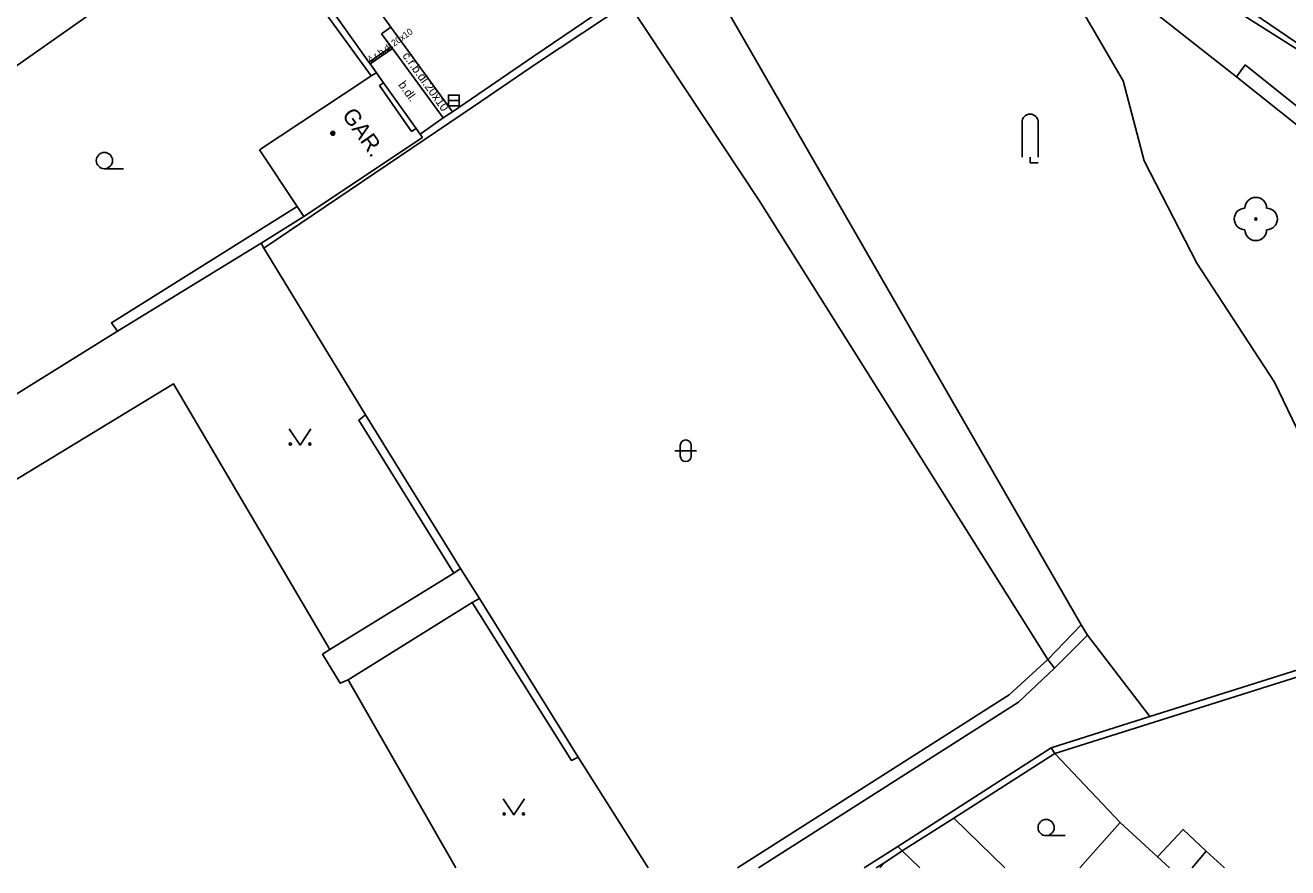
# Model space of a CAD drawing. Extents: x -600391 to -599491, y -1160176 to -1159402.
# Drawn here: x -599722.1 to -599663.7, y -1160176.1 to -1160137.1 of the extents above; entities that cross this region are included whole.
import ezdxf

# ---------------------------------------------------------------- set-up
doc = ezdxf.new("R2010")
doc.units = 0
for name, color, linetype in [('Level 10', 7, 'Continuous'), ('Level 11', 7, 'Continuous'), ('Level 21', 7, 'Continuous'), ('Level 22', 7, 'Continuous'), ('Level 27', 7, 'Continuous'), ('Level 36', 7, 'Continuous'), ('Level 39', 7, 'Continuous'), ('Level 40', 7, 'Continuous'), ('Level 41', 7, 'Continuous'), ('Level 5', 7, 'Continuous'), ('Level 6', 7, 'Continuous'), ('Level 7', 7, 'Continuous'), ('Level 8', 7, 'Continuous'), ('Level 9', 7, 'Continuous')]:
    doc.layers.add(name, color=color, linetype=linetype)

msp = doc.modelspace()

# ---------------------------------------------------------------- linework, layer by layer
at = {"layer": 'Level 10'}
for points in [[(-599729.36, -1160103.71), (-599727.49, -1160106.28), (-599726.09, -1160108.2), (-599720.65, -1160115.64), (-599705.17, -1160137.22)], [(-599694.45, -1160135.76), (-599698.57, -1160138.57), (-599702.33, -1160141.13)], [(-599705.17, -1160137.22), (-599702.33, -1160141.13)]]:
    msp.add_lwpolyline(points, dxfattribs=at)
at = {"layer": 'Level 11'}
for p, q in [((-599702.167, -1160176.079), (-599707.15, -1160167.39)), ((-599696.52, -1160170.96), (-599693.276, -1160176.079)), ((-599679.16, -1160173.78), (-599676.795, -1160176.079)), ((-599680.727, -1160176.079), (-599681.54, -1160175.3)), ((-599667.49, -1160175.31), (-599668.146, -1160176.079)), ((-599666.651, -1160176.079), (-599667.49, -1160175.31)), ((-599682.35, -1160175.83), (-599682.571, -1160176.079))]:
    msp.add_line(p, q, dxfattribs=at)
for points in [[(-599709.31, -1160094.1), (-599694.08, -1160114.15), (-599675.64, -1160129.54), (-599674.089, -1160130.598), (-599661.43, -1160139.23), (-599660.86, -1160139.62), (-599659.78, -1160140.32), (-599650.8, -1160146.17), (-599648.69, -1160147.17), (-599644.71, -1160148.89)], [(-599692.11, -1160132.12), (-599673.27, -1160164.85)], [(-599673.73, -1160133.49), (-599668.38, -1160137.71), (-599666.09, -1160139.52), (-599663.05, -1160141.94), (-599657.72, -1160146.18)], [(-599705.17, -1160137.22), (-599705.6, -1160137.53)], [(-599705.6, -1160137.53), (-599705.16, -1160138.13), (-599705.1, -1160138.21), (-599702.75, -1160141.42)], [(-599706.19, -1160138.84), (-599705.16, -1160138.13)], [(-599706.13, -1160138.92), (-599705.1, -1160138.21)], [(-599665.69, -1160138.97), (-599666.09, -1160139.52)], [(-599657.58, -1160145.46), (-599665.69, -1160138.97)], [(-599703.82, -1160142.17), (-599702.75, -1160141.42), (-599702.45, -1160141.21), (-599702.33, -1160141.13)], [(-599688.15, -1160145.23), (-599674.81, -1160166.46)], [(-599711.16, -1160147.21), (-599711.04, -1160147.44)], [(-599711.04, -1160147.44), (-599706.35, -1160155.14)], [(-599707.99, -1160165.99), (-599715.22, -1160153.71), (-599749.25, -1160174.4)], [(-599702.27, -1160162.46), (-599706.66, -1160155.39), (-599706.35, -1160155.14)], [(-599706.35, -1160155.14), (-599701.96, -1160162.24)], [(-599702.27, -1160162.46), (-599701.96, -1160162.24)], [(-599701.96, -1160162.24), (-599701.08, -1160163.64)], [(-599707.99, -1160165.99), (-599702.27, -1160162.46)], [(-599701.42, -1160163.81), (-599707.15, -1160167.39)], [(-599701.08, -1160163.64), (-599701.42, -1160163.81)], [(-599696.52, -1160170.96), (-599696.83, -1160171.12), (-599701.42, -1160163.81)], [(-599701.08, -1160163.64), (-599696.52, -1160170.96)], [(-599674.81, -1160166.46), (-599673.27, -1160164.85)], [(-599673.27, -1160164.85), (-599672.98, -1160165.32)], [(-599674.5, -1160166.86), (-599672.98, -1160165.32)], [(-599672.98, -1160165.32), (-599670.09, -1160169.08)], [(-599707.15, -1160167.39), (-599707.51, -1160167.55), (-599708.33, -1160166.21), (-599707.99, -1160165.99)], [(-599689.153, -1160176.079), (-599676.6, -1160168.08), (-599674.81, -1160166.46)], [(-599688.183, -1160176.079), (-599676.16, -1160168.43), (-599674.5, -1160166.86)], [(-599674.81, -1160166.46), (-599674.5, -1160166.86)], [(-599674.49, -1160170.79), (-599674.65, -1160170.54)], [(-599671.47, -1160173.99), (-599674.49, -1160170.79)], [(-599667.49, -1160175.31), (-599668.56, -1160174.31), (-599669.74, -1160175.58)], [(-599681.75, -1160175.09), (-599681.54, -1160175.3)]]:
    msp.add_lwpolyline(points, dxfattribs=at)
at = {"layer": 'Level 21'}
msp.add_lwpolyline([(-599632.22, -1160163.23), (-599625.63, -1160162.75), (-599627.08, -1160161.05), (-599631.51, -1160158.07), (-599634.33, -1160155.48), (-599639.05, -1160154.4), (-599647.01, -1160155.58), (-599651.94, -1160159.14), (-599660.68, -1160161.21), (-599664.34, -1160153.64), (-599667.93, -1160148.13), (-599670.36, -1160143.4), (-599671.33, -1160139.71), (-599675.67, -1160132.25), (-599678.77, -1160130.69), (-599683.2, -1160135.35), (-599690.37, -1160125.58), (-599695.06, -1160124.12), (-599698.92, -1160119.17), (-599710.69, -1160100.66)], dxfattribs=at)
at = {"layer": 'Level 22'}
msp.add_circle((-599665.2, -1160146.09), 0.05, dxfattribs=at)
for centre, start, end in [((-599665.2, -1160145.59), 0, 180), ((-599665.7, -1160146.09), 90, 270), ((-599664.7, -1160146.09), 270, 90), ((-599665.2, -1160146.59), 180, 0)]:
    msp.add_arc(centre, 0.5, start, end, dxfattribs=at)
at = {"layer": 'Level 27'}
msp.add_line((-599702.51, -1160140.61), (-599702.01, -1160140.61), dxfattribs=at)
msp.add_lwpolyline([(-599702.51, -1160140.86), (-599702.01, -1160140.86), (-599702.01, -1160140.36), (-599702.51, -1160140.36)], close=True, dxfattribs=at)
at = {"layer": 'Level 36'}
for p, q in [((-599676.005, -1160141.615), (-599676.005, -1160143.24)), ((-599675.255, -1160141.615), (-599675.255, -1160143.24)), ((-599718.41, -1160143.765), (-599717.535, -1160143.765)), ((-599692.046, -1160156.806), (-599691.046, -1160156.806)), ((-599691.796, -1160156.556), (-599691.796, -1160157.056)), ((-599691.296, -1160156.556), (-599691.296, -1160157.056)), ((-599674.89, -1160174.595), (-599674.015, -1160174.595))]:
    msp.add_line(p, q, dxfattribs=at)
for points in [[(-599675.63, -1160143.24), (-599675.63, -1160143.49), (-599675.255, -1160143.49)], [(-599709.87, -1160155.79), (-599709.37, -1160156.54), (-599708.87, -1160155.79)], [(-599699.99, -1160172.89), (-599699.49, -1160173.64), (-599698.99, -1160172.89)]]:
    msp.add_lwpolyline(points, dxfattribs=at)
for centre, radius in [((-599718.41, -1160143.39), 0.375), ((-599709.82, -1160156.49), 0.05), ((-599708.921, -1160156.49), 0.05), ((-599699.94, -1160173.59), 0.05), ((-599699.041, -1160173.59), 0.05), ((-599674.89, -1160174.22), 0.375)]:
    msp.add_circle(centre, radius, dxfattribs=at)
for centre, radius, start, end in [((-599675.63, -1160141.615), 0.375, 0, 180), ((-599691.546, -1160156.556), 0.25, 0, 180), ((-599691.546, -1160157.056), 0.25, 180, 0)]:
    msp.add_arc(centre, radius, start, end, dxfattribs=at)
at = {"layer": 'Level 39'}
for radius in [0.09, 0.0398]:
    msp.add_circle((-599707.86, -1160142.13), radius, dxfattribs=at)
at = {"layer": 'Level 5'}
for p, q in [((-599673.331, -1160176.079), (-599671.47, -1160173.99)), ((-599669.74, -1160175.58), (-599669.182, -1160176.079))]:
    msp.add_line(p, q, dxfattribs=at)
for points in [[(-599715.89, -1160134.37), (-599726.44, -1160141.79)], [(-599711.24, -1160142.9), (-599706.42, -1160139.7), (-599706.08, -1160139.48), (-599705.84, -1160139.33)], [(-599705.84, -1160139.33), (-599705.51, -1160139.8), (-599704.01, -1160141.91), (-599703.82, -1160142.17), (-599703.71, -1160142.32)], [(-599705.51, -1160139.8), (-599705.7, -1160139.92)], [(-599704.22, -1160142.05), (-599705.7, -1160139.92)], [(-599703.71, -1160142.32), (-599709.2, -1160145.98)], [(-599704.22, -1160142.05), (-599704.01, -1160141.91)], [(-599709.2, -1160145.98), (-599709.5, -1160145.52), (-599711.24, -1160142.9)], [(-599671.47, -1160173.99), (-599669.74, -1160175.58)]]:
    msp.add_lwpolyline(points, dxfattribs=at)
at = {"layer": 'Level 6'}
msp.add_lwpolyline([(-599704.22, -1160142.05), (-599705.7, -1160139.92)], dxfattribs=at)
at = {"layer": 'Level 7'}
for p, q in [((-599681.75, -1160175.09), (-599683.302, -1160176.079)), ((-599682.741, -1160176.079), (-599682.35, -1160175.83))]:
    msp.add_line(p, q, dxfattribs=at)
for points in [[(-599714.88, -1160127.38), (-599714.52, -1160127.12), (-599706.19, -1160138.84), (-599706.13, -1160138.92), (-599705.84, -1160139.33)], [(-599706.08, -1160139.48), (-599714.88, -1160127.38)], [(-599698.39, -1160138.87), (-599694.21, -1160136.1), (-599688.15, -1160145.23)], [(-599701.36, -1160140.89), (-599711.04, -1160147.44)], [(-599709.5, -1160145.52), (-599718.08, -1160150.89), (-599717.81, -1160151.27)], [(-599709.2, -1160145.98), (-599711.16, -1160147.21)], [(-599711.16, -1160147.21), (-599717.81, -1160151.27)], [(-599717.81, -1160151.27), (-599722.71, -1160154.32)], [(-599657.25, -1160165.03), (-599670.09, -1160169.08)], [(-599674.49, -1160170.79), (-599657.16, -1160165.33)], [(-599670.09, -1160169.08), (-599674.65, -1160170.54)], [(-599674.65, -1160170.54), (-599681.75, -1160175.09)], [(-599679.16, -1160173.78), (-599674.49, -1160170.79)], [(-599681.54, -1160175.3), (-599679.16, -1160173.78)], [(-599681.54, -1160175.3), (-599682.35, -1160175.83)]]:
    msp.add_lwpolyline(points, dxfattribs=at)
at = {"layer": 'Level 8'}
msp.add_lwpolyline([(-599701.36, -1160140.89), (-599698.39, -1160138.87)], dxfattribs=at)
at = {"layer": 'Level 9'}
msp.add_lwpolyline([(-599666.08, -1160136.48), (-599661.51, -1160139.37), (-599659.84, -1160140.42), (-599650.73, -1160146.18)], dxfattribs=at)

# ---------------------------------------------------------------- texts
at = {"layer": 'Level 40'}
for s, height, rotation, p in [('č.r.b.dl.20x10', 0.3, 35, (-599706.1, -1160138.88)), ('č.r.b.dl.20x10', 0.4, 305.74029, (-599704.66, -1160138.55)), ('b.dl.', 0.4, 305.74029, (-599704.85, -1160139.89))]:
    msp.add_text(s, height=height, rotation=rotation, dxfattribs=at).set_placement(p)
at = {"layer": 'Level 41'}
msp.add_text('GAR.', height=0.75, rotation=305.09748, dxfattribs=at).set_placement((-599707.46, -1160141.29))

doc.saveas('drawing.dxf')
